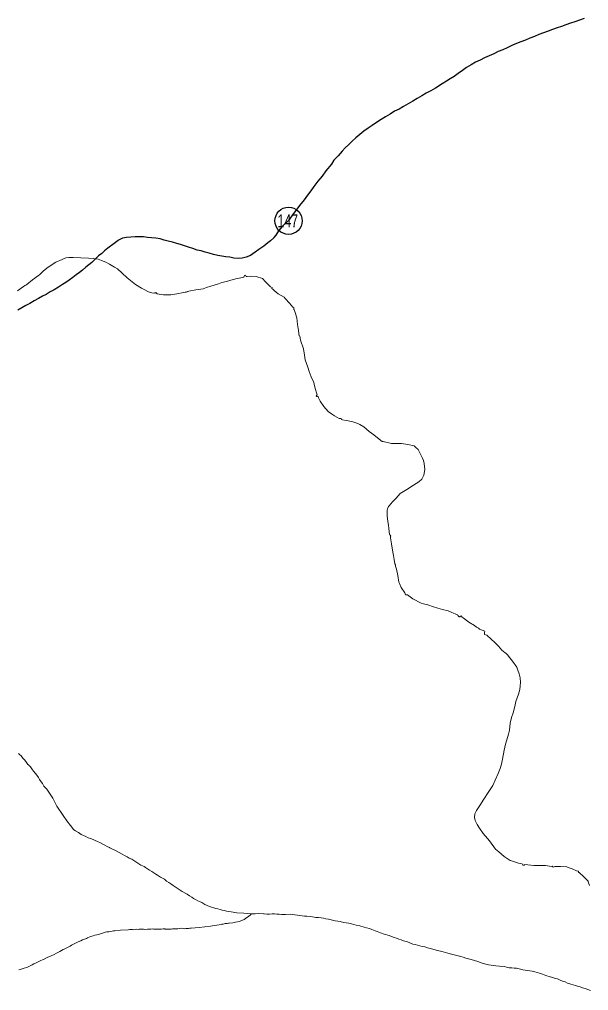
# Model space of a CAD drawing. Extents: x 781.9 to 808.1, y 7453.3 to 7481.5.
# Drawn here: x 785.41 to 788.87, y 7460.95 to 7466.86 of the extents above; entities that cross this region are included whole.
import ezdxf
from ezdxf.enums import TextEntityAlignment as Align

# ---------------------------------------------------------------- set-up
doc = ezdxf.new("R2010")
doc.units = 0
doc.header["$LTSCALE"] = 0.032
for name, pattern in [('DOTTED', [1.5, 0.3, -1.2]), ('LONG_DASHED', [7.5, 6, -1.5]), ('MEDIUM_DASHED', [4.5, 3, -1.5])]:
    doc.linetypes.add(name, pattern=pattern)
for name, color, linetype, lineweight in [('13', 7, 'Continuous', 25), ('18', 7, 'DOTTED', 13), ('19', 7, 'DOTTED', 13), ('4', 7, 'LONG_DASHED', 25), ('6', 7, 'MEDIUM_DASHED', 13), ('7', 7, 'DOTTED', 13)]:
    doc.layers.add(name, color=color, linetype=linetype, lineweight=lineweight)
doc.layers.add('61', color=7, linetype='Continuous')

msp = doc.modelspace()

# ---------------------------------------------------------------- linework, layer by layer
at = {"layer": '13'}
msp.add_circle((787.0487, 7465.6333), 0.083, dxfattribs=at)
msp.add_circle((787.0487, 7465.6333), 0.083, dxfattribs=at)
msp.add_circle((787.0487, 7465.6333), 0.083, dxfattribs=at)
at = {"layer": '18'}
msp.add_lwpolyline([(786.4256, 7465.1989), (786.4191, 7465.1981), (786.4069, 7465.1965), (786.3981, 7465.194), (786.3802, 7465.19), (786.3559, 7465.186), (786.3324, 7465.1819)], dxfattribs=at)
at = {"layer": '19'}
for points in [[(785.8733, 7465.402), (785.8634, 7465.4032), (785.8298, 7465.4056), (785.7842, 7465.408), (785.7378, 7465.4104), (785.7106, 7465.4104), (785.6922, 7465.408), (785.6698, 7465.3976), (785.6314, 7465.3808), (785.6026, 7465.3632), (785.577, 7465.344), (785.5554, 7465.3256), (785.5321, 7465.3043), (785.5265, 7465.2995), (785.49, 7465.2743), (785.4543, 7465.2459), (785.4487, 7465.241), (785.443, 7465.2386), (785.4414, 7465.237), (785.4357, 7465.2338), (785.3992, 7465.207)], [(786.3324, 7465.1819), (786.2862, 7465.1827), (786.2489, 7465.1884), (786.2407, 7465.1956), (786.2343, 7465.1916), (786.2294, 7465.194), (786.227, 7465.1916), (786.2067, 7465.1973), (786.1921, 7465.203), (786.1726, 7465.2135), (786.154, 7465.2224), (786.1159, 7465.2459), (786.0858, 7465.2688), (786.0666, 7465.2864), (786.0354, 7465.3144), (786.0074, 7465.34), (785.9898, 7465.3512), (785.9578, 7465.3696), (785.9354, 7465.3808), (785.909, 7465.392), (785.8898, 7465.4), (785.8733, 7465.402)], [(787.8729, 7464.1555), (787.8688, 7464.1733), (787.8607, 7464.1911), (787.842, 7464.2317), (787.8363, 7464.2414), (787.8234, 7464.2535), (787.8128, 7464.2633), (787.7748, 7464.2706), (787.7358, 7464.2763), (787.6758, 7464.2779), (787.658, 7464.2803), (787.6402, 7464.2852), (787.6239, 7464.2892), (787.6183, 7464.2901), (787.5899, 7464.3119), (787.568, 7464.3306), (787.5526, 7464.3403), (787.5396, 7464.3508), (787.5055, 7464.3792), (787.4821, 7464.393), (787.4707, 7464.3995), (787.4326, 7464.4108), (787.3986, 7464.4182), (787.3775, 7464.4214), (787.371, 7464.4238), (787.3685, 7464.4287), (787.3564, 7464.4303), (787.3272, 7464.4457), (787.3101, 7464.4579), (787.2891, 7464.4717), (787.2639, 7464.5033), (787.2412, 7464.5349), (787.2307, 7464.5552), (787.2291, 7464.5641), (787.221, 7464.5632), (787.2177, 7464.5649), (787.2169, 7464.5673), (787.2234, 7464.573), (787.2186, 7464.5852), (787.2129, 7464.6063), (787.2072, 7464.6273), (787.2024, 7464.6476), (787.1861, 7464.6825), (787.1732, 7464.7149), (787.166, 7464.7413), (787.15, 7464.7869), (787.146, 7464.8157), (787.1388, 7464.8541), (787.1204, 7464.9062), (787.118, 7464.9191), (787.1188, 7464.9232), (787.1172, 7464.9297), (787.1131, 7464.9321), (787.1099, 7464.9476), (787.1083, 7464.9646), (787.1042, 7464.989), (787.1018, 7465.0027), (787.0978, 7465.0424), (787.0872, 7465.0814), (787.083, 7465.0919), (787.0799, 7465.0927), (787.0799, 7465.1024), (787.0742, 7465.1073), (787.0548, 7465.1324), (787.0272, 7465.1608), (787.0215, 7465.1673), (786.9851, 7465.1876), (786.9607, 7465.2086), (786.9526, 7465.2168), (786.9469, 7465.2216), (786.9477, 7465.2264), (786.938, 7465.2305), (786.9072, 7465.2621), (786.8902, 7465.2808), (786.8505, 7465.2938), (786.8181, 7465.297), (786.797, 7465.2938), (786.7904, 7465.2938), (786.7872, 7465.3019), (786.7799, 7465.2994), (786.7751, 7465.2897), (786.7467, 7465.284), (786.7272, 7465.2792), (786.7102, 7465.2751), (786.6714, 7465.2638), (786.6413, 7465.2573), (786.6218, 7465.2483), (786.5748, 7465.2346), (786.5489, 7465.2265), (786.5286, 7465.2192), (786.484, 7465.2127), (786.4419, 7465.2054), (786.4321, 7465.203), (786.4305, 7465.1997), (786.4256, 7465.1989)], [(787.7687, 7463.9978), (787.8087, 7464.0226), (787.8416, 7464.0434), (787.86, 7464.0602), (787.8721, 7464.085), (787.8785, 7464.1186), (787.8729, 7464.1555)], [(788.2631, 7462.1524), (788.2912, 7462.1956), (788.3064, 7462.2284), (788.3249, 7462.2676), (788.3361, 7462.298), (788.345, 7462.3252), (788.3514, 7462.3556), (788.3603, 7462.4092), (788.3684, 7462.4476), (788.3772, 7462.474), (788.3869, 7462.5084), (788.3926, 7462.5315), (788.3974, 7462.5745), (788.4047, 7462.6089), (788.4159, 7462.6369), (788.4256, 7462.6761), (788.432, 7462.7073), (788.4481, 7462.7513), (788.4554, 7462.7801), (788.4578, 7462.8017), (788.4602, 7462.8217), (788.4578, 7462.8505), (788.4509, 7462.8745), (788.4436, 7462.8972), (788.438, 7462.9158), (788.412, 7462.9523), (788.3877, 7462.9823), (788.3828, 7462.9888), (788.3698, 7463.0001), (788.3674, 7463.0021), (788.3474, 7463.0189), (788.3258, 7463.0437), (788.3034, 7463.0661), (788.281, 7463.0861), (788.2547, 7463.1104), (788.2401, 7463.1136), (788.2417, 7463.1241), (788.2409, 7463.1274), (788.2433, 7463.1347), (788.2109, 7463.1477), (788.2044, 7463.1525), (788.1931, 7463.1598), (788.1793, 7463.1688), (788.1461, 7463.1898), (788.112, 7463.215), (788.1055, 7463.219), (788.099, 7463.2271), (788.0917, 7463.2223), (788.0861, 7463.2215), (788.0796, 7463.2304), (788.0764, 7463.2344), (788.0618, 7463.2401), (788.0415, 7463.249), (788.0188, 7463.2588), (787.9855, 7463.2669), (787.9567, 7463.2757), (787.9295, 7463.2821), (787.8959, 7463.2949), (787.8688, 7463.3009), (787.855, 7463.3042), (787.8039, 7463.3309), (787.7715, 7463.356), (787.761, 7463.356), (787.7569, 7463.369), (787.7342, 7463.4015), (787.7229, 7463.4258), (787.7188, 7463.4331), (787.7131, 7463.4728), (787.705, 7463.5117), (787.7002, 7463.5312), (787.6985, 7463.5336), (787.7001, 7463.5385), (787.6961, 7463.544), (787.692, 7463.5701), (787.6872, 7463.5944), (787.6831, 7463.6163), (787.675, 7463.6658), (787.6693, 7463.7031), (787.6685, 7463.7104), (787.6701, 7463.7128), (787.6677, 7463.7184), (787.6653, 7463.7225), (787.6637, 7463.7241), (787.6588, 7463.7598), (787.6564, 7463.7809), (787.6531, 7463.8028), (787.6475, 7463.8377), (787.6491, 7463.8717), (787.6499, 7463.8798), (787.6556, 7463.8928), (787.6605, 7463.8986), (787.6806, 7463.9226), (787.703, 7463.945), (787.7286, 7463.9721), (787.7687, 7463.9978)], [(788.1837, 7461.982), (788.1805, 7462.0012), (788.1822, 7462.022), (788.1918, 7462.0428), (788.2126, 7462.074), (788.2375, 7462.1124), (788.2631, 7462.1524)], [(788.8798, 7461.587), (788.8724, 7461.6081), (788.8709, 7461.6121), (788.8441, 7461.6413), (788.8174, 7461.6648), (788.8133, 7461.6656), (788.8133, 7461.6713), (788.8117, 7461.6737), (788.8093, 7461.6745), (788.8012, 7461.6761), (788.7736, 7461.6883), (788.7509, 7461.6956), (788.742, 7461.6989), (788.7039, 7461.7021), (788.6682, 7461.7021), (788.6601, 7461.698), (788.6576, 7461.7005), (788.6528, 7461.7037), (788.6496, 7461.7029), (788.6131, 7461.707), (788.5904, 7461.707), (788.5815, 7461.707), (788.5417, 7461.7078), (788.5044, 7461.7118), (788.485, 7461.7134), (788.4825, 7461.7077), (788.4744, 7461.7102), (788.4752, 7461.7167), (788.4598, 7461.7199), (788.4477, 7461.7232), (788.4234, 7461.7313), (788.399, 7461.7386), (788.3966, 7461.7394), (788.3601, 7461.7629), (788.3276, 7461.7905), (788.3082, 7461.8083), (788.2709, 7461.8578), (788.2596, 7461.8732), (788.2336, 7461.9032), (788.2109, 7461.9348), (788.1957, 7461.958), (788.1837, 7461.982)]]:
    msp.add_lwpolyline(points, dxfattribs=at)
at = {"layer": '4'}
for points in [[(788.8466, 7466.8642), (788.819, 7466.8545), (788.7914, 7466.8448), (788.7639, 7466.8367), (788.7363, 7466.8261), (788.7104, 7466.8164), (788.6828, 7466.8075), (788.6552, 7466.7969), (788.6277, 7466.788), (788.6001, 7466.7775), (788.5725, 7466.7669), (788.545, 7466.7548), (788.5174, 7466.745), (788.4898, 7466.7337), (788.4623, 7466.7223), (788.4347, 7466.7126), (788.4071, 7466.6996), (788.3796, 7466.6867), (788.352, 7466.6745), (788.3244, 7466.6631), (788.2969, 7466.6502), (788.2693, 7466.6372), (788.2418, 7466.625), (788.2142, 7466.6113), (788.1866, 7466.5991), (788.1591, 7466.5829), (788.1315, 7466.5666), (788.1063, 7466.548), (788.0804, 7466.5302), (788.0561, 7466.5123), (788.031, 7466.4969), (788.0091, 7466.4824), (787.9839, 7466.467), (787.9418, 7466.441), (787.9142, 7466.4248), (787.8866, 7466.4094), (787.8591, 7466.3932), (787.8315, 7466.3769), (787.8039, 7466.3615), (787.7764, 7466.3453), (787.7488, 7466.3299), (787.7212, 7466.3137), (787.6937, 7466.2999), (787.6661, 7466.2821), (787.6385, 7466.2667), (787.611, 7466.2488), (787.5834, 7466.231), (787.5582, 7466.2132), (787.5331, 7466.1961), (787.5072, 7466.1783), (787.4812, 7466.1589), (787.4577, 7466.1386), (787.4351, 7466.1175), (787.4139, 7466.0964), (787.3936, 7466.077), (787.375, 7466.0567), (787.3499, 7466.0283), (787.3248, 7466.0016), (787.3094, 7465.9781), (787.2753, 7465.9375), (787.2526, 7465.9051), (787.2275, 7465.8743), (787.2031, 7465.8419), (787.1837, 7465.8159), (787.1634, 7465.7884), (787.1439, 7465.7608)], [(787.1439, 7465.7608), (787.1151, 7465.7256), (787.1111, 7465.7201), (787.0783, 7465.6785), (787.0479, 7465.6353), (787.0095, 7465.5993), (786.9879, 7465.5713)], [(786.9879, 7465.5713), (786.9703, 7465.5465), (786.9583, 7465.5305), (786.9591, 7465.5297), (786.938, 7465.5119), (786.9229, 7465.4987), (786.8981, 7465.4787), (786.8677, 7465.4579), (786.8453, 7465.4411), (786.8164, 7465.4227), (786.7905, 7465.4122), (786.7662, 7465.4057), (786.7418, 7465.404), (786.7159, 7465.4065), (786.6899, 7465.4113), (786.6656, 7465.4138), (786.6413, 7465.417), (786.617, 7465.4227), (786.591, 7465.4283), (786.5651, 7465.4357), (786.5408, 7465.4421), (786.5164, 7465.4494), (786.4921, 7465.4551), (786.4662, 7465.4648), (786.4402, 7465.473), (786.4159, 7465.4803), (786.3916, 7465.4883), (786.3673, 7465.4948), (786.3413, 7465.5029), (786.3153, 7465.5086), (786.2911, 7465.5159), (786.2667, 7465.5224), (786.2408, 7465.5265), (786.2148, 7465.5289), (786.1889, 7465.5313), (786.1646, 7465.5346), (786.1403, 7465.5354), (786.1143, 7465.5354), (786.0884, 7465.5338), (786.0624, 7465.5305), (786.0381, 7465.5265), (786.0138, 7465.5143), (786.0113, 7465.5135), (785.9878, 7465.4956), (785.9489, 7465.4673), (785.9286, 7465.451), (785.9116, 7465.434), (785.8922, 7465.4194), (785.8808, 7465.4097), (785.8733, 7465.402)], [(785.8733, 7465.402), (785.8516, 7465.3797), (785.8151, 7465.3505), (785.7948, 7465.3335), (785.7762, 7465.3181), (785.7551, 7465.3035), (785.7348, 7465.2873), (785.713, 7465.2719), (785.6927, 7465.2573), (785.6716, 7465.2443), (785.6473, 7465.2297), (785.6222, 7465.2127), (785.597, 7465.1997), (785.5735, 7465.1851), (785.55, 7465.1738), (785.5257, 7465.16), (785.4997, 7465.1454), (785.4738, 7465.13), (785.4495, 7465.117), (785.4252, 7465.1024), (785.4008, 7465.0886)]]:
    msp.add_lwpolyline(points, dxfattribs=at)
at = {"layer": '6'}
for points in [[(785.554, 7462.1991), (785.5532, 7462.2023), (785.55, 7462.208), (785.5419, 7462.2177), (785.533, 7462.2323), (785.5265, 7462.2429), (785.5168, 7462.2583), (785.5086, 7462.268), (785.4965, 7462.2826), (785.4892, 7462.2899), (785.4778, 7462.3085), (785.4721, 7462.3142), (785.4705, 7462.3158), (785.4673, 7462.319), (785.4649, 7462.3207), (785.4624, 7462.3231), (785.4527, 7462.3345), (785.443, 7462.3483), (785.4316, 7462.3612), (785.4203, 7462.375), (785.4113, 7462.3839), (785.4049, 7462.3904)], [(785.6051, 7462.1302), (785.597, 7462.1432), (785.5889, 7462.1553), (785.5775, 7462.1723), (785.576, 7462.1748), (785.5597, 7462.1909), (785.554, 7462.1991)], [(786.82, 7461.4142), (786.7753, 7461.4174), (786.7336, 7461.4198), (786.6984, 7461.4254), (786.6705, 7461.4305), (786.6575, 7461.4337), (786.6445, 7461.4369), (786.6316, 7461.4402), (786.6186, 7461.4434), (786.6056, 7461.4459), (786.5927, 7461.4499), (786.5797, 7461.454), (786.5675, 7461.4581), (786.5391, 7461.471), (786.5197, 7461.4824), (786.5067, 7461.488), (786.4969, 7461.4937), (786.4824, 7461.501), (786.4694, 7461.5075), (786.4589, 7461.5148), (786.4451, 7461.5237), (786.4321, 7461.5326), (786.4281, 7461.5359), (786.4005, 7461.5505), (786.3819, 7461.5626), (786.3713, 7461.5699), (786.3575, 7461.578), (786.3452, 7461.5869), (786.3324, 7461.5959), (786.3194, 7461.604), (786.3064, 7461.6121), (786.2959, 7461.6226), (786.2927, 7461.6251), (786.2692, 7461.6364), (786.2505, 7461.6486), (786.2399, 7461.6559), (786.2278, 7461.6632), (786.2156, 7461.6713), (786.2026, 7461.6794), (786.1905, 7461.6883), (786.1767, 7461.6964), (786.1686, 7461.7013), (786.1491, 7461.711), (786.1313, 7461.7223), (786.1183, 7461.7304), (786.107, 7461.7377), (786.094, 7461.7466), (786.0786, 7461.7532), (786.0665, 7461.7604), (786.0502, 7461.7694), (786.0357, 7461.7775), (785.9997, 7461.7983), (785.9613, 7461.8151), (785.9578, 7461.818), (785.944, 7461.8237), (785.9295, 7461.831), (785.9173, 7461.8383), (785.8994, 7461.848), (785.8897, 7461.8529), (785.8662, 7461.8626), (785.8451, 7461.8715), (785.8289, 7461.8772), (785.8143, 7461.8837), (785.7997, 7461.8902), (785.7859, 7461.8967), (785.7689, 7461.908), (785.7511, 7461.9186), (785.7422, 7461.9243), (785.721, 7461.951), (785.6994, 7461.9798), (785.6762, 7462.0126), (785.6386, 7462.0694), (785.6254, 7462.0945), (785.6189, 7462.1059), (785.6132, 7462.1172), (785.6051, 7462.1302)], [(787.1456, 7461.4005), (787.131, 7461.4021), (787.1164, 7461.4037), (787.1018, 7461.4061), (787.0872, 7461.407), (787.0726, 7461.4094), (787.0572, 7461.4119), (787.0288, 7461.4102), (787.0061, 7461.4094), (786.9916, 7461.411), (786.977, 7461.4126), (786.9624, 7461.4134), (786.9478, 7461.4134), (786.9316, 7461.4126), (786.9153, 7461.411), (786.9007, 7461.4134), (786.8951, 7461.4135), (786.8683, 7461.4151), (786.8456, 7461.4142), (786.82, 7461.4142)], [(787.2461, 7461.3891), (787.2315, 7461.3916), (787.2169, 7461.3923), (787.2145, 7461.3924), (787.1845, 7461.3972), (787.1602, 7461.3988), (787.1456, 7461.4005)], [(788.8855, 7460.9465), (788.8693, 7460.9529), (788.8531, 7460.9586), (788.8369, 7460.9627), (788.8223, 7460.9683), (788.8077, 7460.9724), (788.7955, 7460.9765), (788.7671, 7460.9854), (788.7468, 7460.9926), (788.7315, 7460.9991), (788.7152, 7461.004), (788.7006, 7461.0105), (788.686, 7461.017), (788.6715, 7461.021), (788.6569, 7461.0259), (788.6414, 7461.0292), (788.6147, 7461.0389), (788.5944, 7461.047), (788.5758, 7461.0527), (788.5612, 7461.0575), (788.5466, 7461.0608), (788.532, 7461.064), (788.5174, 7461.0665), (788.502, 7461.0697), (788.4736, 7461.0737), (788.4509, 7461.0794), (788.4363, 7461.0826), (788.4217, 7461.0834), (788.4071, 7461.0851), (788.3909, 7461.0859), (788.3747, 7461.09), (788.3642, 7461.0924), (788.3326, 7461.0948), (788.3099, 7461.0972), (788.2953, 7461.0989), (788.2807, 7461.1021), (788.2645, 7461.1037), (788.2482, 7461.107), (788.232, 7461.1118), (788.2263, 7461.1135), (788.1996, 7461.124), (788.1793, 7461.1305), (788.1607, 7461.1354), (788.1445, 7461.1402), (788.1282, 7461.1443), (788.112, 7461.1499), (788.0974, 7461.1532), (788.0885, 7461.1556), (788.0634, 7461.1621), (788.0407, 7461.1678), (788.0175, 7461.175), (787.9887, 7461.1814), (787.9463, 7461.1926), (787.9271, 7461.1982), (787.8931, 7461.2075), (787.8769, 7461.2124), (787.8623, 7461.2156), (787.8477, 7461.2189), (787.8331, 7461.2237), (787.8185, 7461.227), (787.8039, 7461.2294), (787.8015, 7461.2302), (787.7715, 7461.2424), (787.7488, 7461.2489), (787.7342, 7461.2545), (787.7196, 7461.2586), (787.705, 7461.2651), (787.6904, 7461.2699), (787.6758, 7461.2756), (787.6604, 7461.2821), (787.6304, 7461.2902), (787.6085, 7461.2983), (787.5883, 7461.3056), (787.5753, 7461.3105), (787.5558, 7461.3178), (787.5404, 7461.3235), (787.5218, 7461.3283), (787.508, 7461.3324), (787.4829, 7461.3405), (787.4602, 7461.3453), (787.4456, 7461.3494), (787.431, 7461.3534), (787.4148, 7461.3559), (787.3986, 7461.3583), (787.384, 7461.3616), (787.3694, 7461.3656), (787.3637, 7461.3664), (787.3321, 7461.3721), (787.3078, 7461.3778), (787.2915, 7461.3818), (787.2753, 7461.3842), (787.2607, 7461.3867), (787.2461, 7461.3891)]]:
    msp.add_lwpolyline(points, dxfattribs=at)
at = {"layer": '7'}
for points in [[(786.82, 7461.4142), (786.8167, 7461.4072), (786.8051, 7461.3972), (786.7953, 7461.3915), (786.7783, 7461.3802), (786.754, 7461.3681), (786.7483, 7461.3672), (786.737, 7461.3648), (786.7256, 7461.3624), (786.7094, 7461.3583), (786.6875, 7461.3567), (786.6835, 7461.3559), (786.6737, 7461.3543), (786.6624, 7461.3543), (786.651, 7461.3518), (786.6421, 7461.3502), (786.639, 7461.3495), (786.5736, 7461.3387), (786.5042, 7461.3311), (786.4556, 7461.3267), (786.4483, 7461.3259), (786.4402, 7461.3251), (786.4321, 7461.3242), (786.424, 7461.3242), (786.4159, 7461.3234), (786.4078, 7461.3251), (786.3948, 7461.3259), (786.3746, 7461.3227), (786.3738, 7461.3226), (786.3656, 7461.3226), (786.3575, 7461.3226), (786.3494, 7461.3226), (786.3413, 7461.3218), (786.3332, 7461.321), (786.3219, 7461.321), (786.2967, 7461.321), (786.2943, 7461.3218), (786.2846, 7461.3218), (786.2748, 7461.321), (786.2651, 7461.321), (786.2521, 7461.321), (786.2302, 7461.3194), (786.2262, 7461.3202), (786.2181, 7461.3218), (786.21, 7461.3194), (786.2019, 7461.3194), (786.1905, 7461.3194), (786.1735, 7461.3193), (786.1662, 7461.3194), (786.1565, 7461.3194), (786.1467, 7461.3194), (786.1386, 7461.3194), (786.1321, 7461.3186), (786.1257, 7461.321), (786.1038, 7461.317), (786.0981, 7461.3178), (786.09, 7461.3186), (786.0819, 7461.3178), (786.0717, 7461.3165), (786.0251, 7461.3149), (785.9918, 7461.3097), (785.9886, 7461.3105), (785.983, 7461.3097), (785.9659, 7461.3065), (785.9538, 7461.3048), (785.9424, 7461.3048), (785.9319, 7461.3024), (785.9165, 7461.2967), (785.8913, 7461.2886), (785.8808, 7461.2862), (785.8695, 7461.2837), (785.8597, 7461.2805), (785.8435, 7461.2748), (785.8249, 7461.2667), (785.8176, 7461.2642), (785.8062, 7461.2594), (785.7949, 7461.2553), (785.7835, 7461.2497), (785.7673, 7461.2432), (785.7437, 7461.2319), (785.7349, 7461.227), (785.7267, 7461.2221), (785.7187, 7461.2172), (785.7032, 7461.2083), (785.6822, 7461.1994), (785.6765, 7461.1961), (785.6659, 7461.1905), (785.6554, 7461.1848), (785.64, 7461.1767), (785.6173, 7461.1646), (785.6084, 7461.1606), (785.5987, 7461.1556), (785.5841, 7461.1491), (785.5573, 7461.1362), (785.5516, 7461.1337)], [(785.5516, 7461.1337), (785.5403, 7461.1297), (785.5241, 7461.1216), (785.5005, 7461.1094), (785.4981, 7461.1086), (785.4884, 7461.1037), (785.4787, 7461.0989)], [(785.4787, 7461.0989), (785.4721, 7461.0956), (785.4592, 7461.0883), (785.4324, 7461.0802), (785.4268, 7461.0786), (785.4154, 7461.0745), (785.4057, 7461.0721)]]:
    msp.add_lwpolyline(points, dxfattribs=at)

# ---------------------------------------------------------------- texts
at = {"layer": '61', "width": 0.7}
msp.add_text('147', height=0.08, dxfattribs=at).set_placement((787.0438, 7465.5929), align=Align.CENTER)

doc.saveas('drawing.dxf')
